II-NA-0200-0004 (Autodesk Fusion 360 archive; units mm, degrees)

design "II-NA-0200-0004" references "POWER", "LED", "3M Screw", "2 ports ethernet vertical", "Digitus_DN-651107_LAN-Switch 19.5mm"
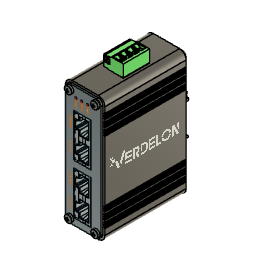
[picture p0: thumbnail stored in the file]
sketch "Sketch1" plane through (0, 0, 0) normal (0, 1, 0) x axis (1, 0, 0)
  line L1 (25, 0) -> (5, 0)
  line L2 (30, -90) -> (30, -5)
  line L3 (5, -95) -> (25, -95)
  line L4 (0, -5) -> (0, -90)
  arc A1 centre (5, -90) radius 5 clockwise from (5, -95) to (0, -90)
  arc A2 centre (25, -90) radius 5 clockwise from (30, -90) to (25, -95)
  arc A3 centre (5, -5) radius 5 clockwise from (0, -5) to (5, 0)
  arc A4 centre (25, -5) radius 5 clockwise from (25, 0) to (30, -5)
  point P1 (0, 0)
  point P2 (0, 0)
  point P4 (0, -95)
  point P3 (30, 0)
  horizontal L1
  vertical L2
  horizontal L3
  vertical L4
  coincident P1 P2
  coincident P4 L3
  coincident P4 L4
  tangent L3 A1
  tangent L4 A1
  tangent L2 A2
  tangent L3 A2
  equal A1 A2
  coincident P2 L1
  coincident P2 L4
  tangent L1 A3
  tangent L4 A3
  equal A1 A3
  coincident P3 L1
  coincident P3 L2
  tangent L1 A4
  tangent L2 A4
  equal A1 A4
  dimension "d1" distance P2 P4 = 95
  dimension "d2" distance P2 P3 = 30
  dimension "d3" radius A1 = 5
extrude "Extrude1" new body sketch "Sketch1" along normal blind 65
sketch "Sketch2" plane through (0, 0, 0) normal (0, -1, 0) x axis (1, 0, 0)
  line L1 (5, 95) -> (25, 95)
  line L2 (0, 5) -> (0, 90)
  line L3 (25, 0) -> (5, 0)
  line L4 (30, 90) -> (30, 5)
  line L5 (1.5, 5) -> (1.5, 90)
  line L6 (25, 1.5) -> (5, 1.5)
  line L7 (28.5, 90) -> (28.5, 5)
  line L8 (5, 93.5) -> (25, 93.5)
  line L9 (0, 5) -> (0, 90)
  line L10 (25, 0) -> (5, 0)
  line L11 (30, 90) -> (30, 5)
  line L12 (5, 95) -> (25, 95)
  arc A1 centre (25, 90) radius 5 clockwise from (25, 95) to (30, 90)
  arc A2 centre (5, 90) radius 5 clockwise from (0, 90) to (5, 95)
  arc A3 centre (5, 5) radius 5 clockwise from (5, 0) to (0, 5)
  arc A4 centre (25, 5) radius 5 clockwise from (30, 5) to (25, 0)
  arc A5 centre (5, 5) radius 3.5 clockwise from (5, 1.5) to (1.5, 5)
  arc A6 centre (25, 5) radius 3.5 clockwise from (28.5, 5) to (25, 1.5)
  arc A7 centre (25, 90) radius 3.5 clockwise from (25, 93.5) to (28.5, 90)
  arc A8 centre (5, 90) radius 3.5 clockwise from (1.5, 90) to (5, 93.5)
  arc A9 centre (5, 5) radius 5 clockwise from (5, 0) to (0, 5)
  arc A10 centre (25, 5) radius 5 clockwise from (30, 5) to (25, 0)
  arc A11 centre (25, 90) radius 5 clockwise from (25, 95) to (30, 90)
  arc A12 centre (5, 90) radius 5 clockwise from (0, 90) to (5, 95)
  dimension "d6" = -1.5
  dimension "d7" distance L2 = 0
extrude "Extrude2" cut sketch "Sketch2" against normal blind 1.5
sketch "Sketch3" plane through (0, 65, 0) normal (0, 1, 0) x axis (-1, 0, 0)
  line L1 (-30, 5) -> (-30, 90)
  line L2 (-5, 0) -> (-25, 0)
  line L3 (0, 90) -> (0, 5)
  line L4 (-25, 95) -> (-5, 95)
  line L5 (-28.5, 5) -> (-28.5, 90)
  line L6 (-5, 1.5) -> (-25, 1.5)
  line L7 (-1.5, 90) -> (-1.5, 5)
  line L8 (-25, 93.5) -> (-5, 93.5)
  line L9 (-30, 5) -> (-30, 90)
  line L10 (-5, 0) -> (-25, 0)
  line L11 (0, 90) -> (0, 5)
  line L12 (-25, 95) -> (-5, 95)
  arc A1 centre (-25, 90) radius 5 clockwise from (-30, 90) to (-25, 95)
  arc A2 centre (-25, 5) radius 5 clockwise from (-25, 0) to (-30, 5)
  arc A3 centre (-5, 5) radius 5 clockwise from (0, 5) to (-5, 0)
  arc A4 centre (-5, 90) radius 5 clockwise from (-5, 95) to (0, 90)
  arc A5 centre (-25, 5) radius 3.5 clockwise from (-25, 1.5) to (-28.5, 5)
  arc A6 centre (-5, 5) radius 3.5 clockwise from (-1.5, 5) to (-5, 1.5)
  arc A7 centre (-5, 90) radius 3.5 clockwise from (-5, 93.5) to (-1.5, 90)
  arc A8 centre (-25, 90) radius 3.5 clockwise from (-28.5, 90) to (-25, 93.5)
  arc A9 centre (-25, 5) radius 5 clockwise from (-25, 0) to (-30, 5)
  arc A10 centre (-5, 5) radius 5 clockwise from (0, 5) to (-5, 0)
  arc A11 centre (-5, 90) radius 5 clockwise from (-5, 95) to (0, 90)
  arc A12 centre (-25, 90) radius 5 clockwise from (-30, 90) to (-25, 95)
  dimension "d10" = -1.5
  dimension "d11" distance L1 = 0
extrude "Extrude3" cut sketch "Sketch3" against normal blind 1.5
sketch "Sketch4" plane through (0, 1.5, 0) normal (0, -1, 0) x axis (1, 0, 0)
  line L1 (25, 93.5) -> (5, 93.5)
  line L2 (28.5, 5) -> (28.5, 90)
  line L3 (5, 1.5) -> (25, 1.5)
  line L4 (1.5, 90) -> (1.5, 5)
  line L5 (0, 5) -> (0, 90)
  line L6 (25, 0) -> (5, 0)
  line L7 (30, 90) -> (30, 5)
  line L8 (5, 95) -> (25, 95)
  line L9 (-15.934, 47.5) -> (1.5, 47.5)
  line L10 (15, 105) -> (15, 93.5)
  line L11 (0.5, 85.5) -> (0, 85.5)
  line L12 (0.5, 84.5) -> (0.5, 85.5)
  line L13 (0, 84.5) -> (0.5, 84.5)
  line L14 (0, 85.5) -> (0, 84.5)
  line L15 (0, 84) -> (0, 83)
  line L16 (0, 83) -> (0.5, 83)
  line L17 (0.5, 84) -> (0, 84)
  line L18 (0.5, 83) -> (0.5, 84)
  line L19 (0, 82.5) -> (0, 81.5)
  line L20 (0, 81.5) -> (0.5, 81.5)
  line L21 (0.5, 82.5) -> (0, 82.5)
  line L22 (0.5, 81.5) -> (0.5, 82.5)
  line L23 (0, 79) -> (0.5, 79)
  line L24 (0, 77) -> (0, 76)
  line L25 (0, 78.5) -> (0, 77.5)
  line L26 (0.5, 78.5) -> (0, 78.5)
  line L27 (0.5, 80) -> (0, 80)
  line L28 (0, 76) -> (0.5, 76)
  line L29 (0.5, 76) -> (0.5, 77)
  line L30 (0, 80) -> (0, 79)
  line L31 (0.5, 77) -> (0, 77)
  line L32 (0, 77.5) -> (0.5, 77.5)
  line L33 (0.5, 77.5) -> (0.5, 78.5)
  line L34 (0.5, 79) -> (0.5, 80)
  line L35 (0, 73.5) -> (0.5, 73.5)
  line L36 (0, 71.5) -> (0, 70.5)
  line L37 (0, 73) -> (0, 72)
  line L38 (0.5, 73) -> (0, 73)
  line L39 (0.5, 74.5) -> (0, 74.5)
  line L40 (0, 70.5) -> (0.5, 70.5)
  line L41 (0.5, 70.5) -> (0.5, 71.5)
  line L42 (0, 74.5) -> (0, 73.5)
  line L43 (0.5, 71.5) -> (0, 71.5)
  line L44 (0, 72) -> (0.5, 72)
  line L45 (0.5, 72) -> (0.5, 73)
  line L46 (0.5, 73.5) -> (0.5, 74.5)
  line L47 (0, 23.5) -> (0, 24.5)
  line L48 (0.5, 17.5) -> (0.5, 16.5)
  line L49 (0.5, 19) -> (0.5, 18)
  line L50 (0, 20.5) -> (0, 21.5)
  line L51 (0, 16) -> (0.5, 16)
  line L52 (0.5, 11) -> (0, 11)
  line L53 (0.5, 12) -> (0.5, 11)
  line L54 (0, 12) -> (0.5, 12)
  line L55 (0.5, 15) -> (0, 15)
  line L56 (0, 15) -> (0, 16)
  line L57 (0, 17.5) -> (0.5, 17.5)
  line L58 (0, 19) -> (0.5, 19)
  line L59 (0.5, 16) -> (0.5, 15)
  line L60 (0, 11) -> (0, 12)
  line L61 (0, 22) -> (0, 23)
  line L62 (0.5, 18) -> (0, 18)
  line L63 (0, 13.5) -> (0.5, 13.5)
  line L64 (0.5, 23) -> (0.5, 22)
  line L65 (0.5, 10.5) -> (0.5, 9.5)
  line L66 (0, 10.5) -> (0.5, 10.5)
  line L67 (0.5, 23.5) -> (0, 23.5)
  line L68 (0.5, 12.5) -> (0, 12.5)
  line L69 (0.5, 21.5) -> (0.5, 20.5)
  line L70 (0.5, 16.5) -> (0, 16.5)
  line L71 (0, 12.5) -> (0, 13.5)
  line L72 (0, 16.5) -> (0, 17.5)
  line L73 (0, 24.5) -> (0.5, 24.5)
  line L74 (0.5, 24.5) -> (0.5, 23.5)
  line L75 (0, 21.5) -> (0.5, 21.5)
  line L76 (0.5, 9.5) -> (0, 9.5)
  line L77 (0.5, 13.5) -> (0.5, 12.5)
  line L78 (0, 9.5) -> (0, 10.5)
  line L79 (0, 18) -> (0, 19)
  line L80 (0.5, 22) -> (0, 22)
  line L81 (0.5, 20.5) -> (0, 20.5)
  line L82 (0, 23) -> (0.5, 23)
  line L83 (30, 76) -> (29.5, 76)
  line L84 (30, 70.5) -> (29.5, 70.5)
  line L85 (29.5, 73.5) -> (29.5, 74.5)
  line L86 (30, 84.5) -> (29.5, 84.5)
  line L87 (30, 73) -> (30, 72)
  line L88 (30, 83) -> (29.5, 83)
  line L89 (30, 72) -> (29.5, 72)
  line L90 (30, 73.5) -> (29.5, 73.5)
  line L91 (29.5, 83) -> (29.5, 84)
  line L92 (29.5, 77) -> (30, 77)
  line L93 (30, 71.5) -> (30, 70.5)
  line L94 (30, 78.5) -> (30, 77.5)
  line L95 (29.5, 73) -> (30, 73)
  line L96 (29.5, 82.5) -> (30, 82.5)
  line L97 (30, 81.5) -> (29.5, 81.5)
  line L98 (29.5, 84) -> (30, 84)
  line L99 (29.5, 77.5) -> (29.5, 78.5)
  line L100 (30, 79) -> (29.5, 79)
  line L101 (29.5, 84.5) -> (29.5, 85.5)
  line L102 (30, 77) -> (30, 76)
  line L103 (30, 74.5) -> (30, 73.5)
  line L104 (29.5, 79) -> (29.5, 80)
  line L105 (29.5, 81.5) -> (29.5, 82.5)
  line L106 (30, 80) -> (30, 79)
  line L107 (29.5, 85.5) -> (30, 85.5)
  line L108 (30, 85.5) -> (30, 84.5)
  line L109 (29.5, 76) -> (29.5, 77)
  line L110 (30, 84) -> (30, 83)
  line L111 (29.5, 71.5) -> (30, 71.5)
  line L112 (29.5, 78.5) -> (30, 78.5)
  line L113 (29.5, 70.5) -> (29.5, 71.5)
  line L114 (30, 82.5) -> (30, 81.5)
  line L115 (29.5, 80) -> (30, 80)
  line L116 (29.5, 74.5) -> (30, 74.5)
  line L117 (30, 77.5) -> (29.5, 77.5)
  line L118 (29.5, 72) -> (29.5, 73)
  line L119 (30, 17.5) -> (29.5, 17.5)
  line L120 (29.5, 23.5) -> (30, 23.5)
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  point P22 (1.5, 47.5)
  point P24 (15, 93.5)
  point P26 (0, 85.5)
  point P81 (0, 9.5)
  point P27 (0.5, 85.5)
  point P73 (0.5, 9.5)
  point P28 (0.5, 84.5)
  point P67 (0.5, 10.5)
  point P29 (0, 84.5)
  point P89 (0, 10.5)
  point P30 (0, 83)
  point P91 (0, 12)
  point P31 (0, 84)
  point P86 (0, 11)
  point P32 (0.5, 83)
  point P65 (0.5, 12)
  point P33 (0.5, 84)
  point P77 (0.5, 11)
  point P34 (0, 81.5)
  point P70 (0, 13.5)
  point P35 (0, 82.5)
  point P68 (0, 12.5)
  point P36 (0.5, 81.5)
  point P80 (0.5, 13.5)
  point P37 (0.5, 82.5)
  point P82 (0.5, 12.5)
  point P38 (0, 79)
  point P83 (0, 16)
  point P39 (0.5, 79)
  point P76 (0.5, 16)
  point P40 (0.5, 80)
  point P74 (0.5, 15)
  point P41 (0, 76)
  point P71 (0, 19)
  point P42 (0, 77)
  point P62 (0, 18)
  point P43 (0.5, 77)
  point P63 (0.5, 18)
  point P44 (0, 77.5)
  point P93 (0, 17.5)
  point P45 (0, 78.5)
  point P92 (0, 16.5)
  point P46 (0.5, 78.5)
  point P90 (0.5, 16.5)
  point P47 (0, 80)
  point P96 (0, 15)
  point P48 (0.5, 76)
  point P95 (0.5, 19)
  point P49 (0.5, 77.5)
  point P97 (0.5, 17.5)
  point P50 (0, 73.5)
  point P87 (0, 21.5)
  point P51 (0.5, 73.5)
  point P88 (0.5, 21.5)
  point P52 (0.5, 74.5)
  point P94 (0.5, 20.5)
  point P53 (0, 70.5)
  point P66 (0, 24.5)
  point P54 (0, 71.5)
  point P64 (0, 23.5)
  point P55 (0.5, 71.5)
  point P78 (0.5, 23.5)
  point P56 (0, 72)
  point P72 (0, 23)
  point P57 (0, 73)
  point P75 (0, 22)
  point P58 (0.5, 73)
  point P69 (0.5, 22)
  point P59 (0, 74.5)
  point P79 (0, 20.5)
  point P60 (0.5, 70.5)
  point P84 (0.5, 24.5)
  point P61 (0.5, 72)
  point P85 (0.5, 23)
  point P106 (30, 85.5)
  point P121 (29.5, 85.5)
  point P122 (29.5, 84.5)
  point P118 (30, 84.5)
  point P120 (30, 83)
  point P119 (30, 84)
  point P123 (29.5, 83)
  point P126 (29.5, 84)
  point P125 (30, 81.5)
  point P124 (30, 82.5)
  point P100 (29.5, 81.5)
  point P98 (29.5, 82.5)
  point P102 (30, 79)
  point P99 (29.5, 79)
  point P101 (29.5, 80)
  point P131 (30, 76)
  point P129 (30, 77)
  point P127 (29.5, 77)
  point P130 (30, 77.5)
  point P133 (30, 78.5)
  point P128 (29.5, 78.5)
  point P132 (30, 80)
  point P113 (29.5, 76)
  point P116 (29.5, 77.5)
  point P112 (30, 73.5)
  point P117 (29.5, 73.5)
  point P115 (29.5, 74.5)
  point P114 (30, 70.5)
  point P111 (30, 71.5)
  point P105 (29.5, 71.5)
  point P108 (30, 72)
  point P104 (30, 73)
  point P103 (29.5, 73)
  point P109 (30, 74.5)
  point P110 (29.5, 70.5)
  point P107 (29.5, 72)
  point P169 (30, 18)
  point P134 (29.5, 18)
  point P138 (30, 23.5)
  point P166 (29.5, 12)
  point P139 (30, 24.5)
  point P160 (29.5, 10.5)
  point P140 (30, 12.5)
  point P135 (29.5, 22)
  point P147 (30, 13.5)
  point P136 (30, 19)
  point P155 (30, 23)
  point P148 (29.5, 9.5)
  point P162 (29.5, 15)
  point P168 (30, 22)
  point P157 (29.5, 16)
  point P141 (29.5, 11)
  point P165 (29.5, 23.5)
  point P167 (30, 20.5)
  point P151 (29.5, 13.5)
  point P143 (30, 9.5)
  point P152 (29.5, 12.5)
  point P150 (30, 16)
  point P145 (29.5, 24.5)
  point P142 (29.5, 23)
  point P164 (30, 11)
  point P149 (30, 21.5)
  point P146 (29.5, 21.5)
  point P154 (30, 10.5)
  point P144 (29.5, 16.5)
  point P153 (30, 12)
  point P158 (30, 16.5)
  point P156 (30, 17.5)
  point P163 (29.5, 20.5)
  point P161 (29.5, 19)
  point P159 (30, 15)
  point P137 (29.5, 17.5)
  midpoint L4 P22
  perpendicular L4 L9
  midpoint L1 P24
  perpendicular L8 L10
  horizontal L11
  vertical L12
  horizontal L13
  vertical L14
  coincident L5 P26
  symmetric L9 P26 P81
  symmetric L9 P27 P73
  symmetric L9 P28 P67
  symmetric L9 P29 P89
  symmetric L9 P30 P91
  symmetric L9 P31 P86
  symmetric L9 P32 P65
  symmetric L9 P33 P77
  symmetric L9 P34 P70
  symmetric L9 P35 P68
  symmetric L9 P36 P80
  symmetric L9 P37 P82
  symmetric L9 P38 P83
  symmetric L9 P39 P76
  symmetric L9 P40 P74
  symmetric L9 P41 P71
  symmetric L9 P42 P62
  symmetric L9 P43 P63
  symmetric L9 P44 P93
  symmetric L9 P45 P92
  symmetric L9 P46 P90
  symmetric L9 P47 P96
  symmetric L9 P48 P95
  symmetric L9 P49 P97
  symmetric L9 P50 P87
  symmetric L9 P51 P88
  symmetric L9 P52 P94
  symmetric L9 P53 P66
  symmetric L9 P54 P64
  symmetric L9 P55 P78
  symmetric L9 P56 P72
  symmetric L9 P57 P75
  symmetric L9 P58 P69
  symmetric L9 P59 P79
  symmetric L9 P60 P84
  symmetric L9 P61 P85
  symmetric L10 P26 P106
  symmetric L10 P27 P121
  symmetric L10 P28 P122
  symmetric L10 P29 P118
  symmetric L10 P30 P120
  symmetric L10 P31 P119
  symmetric L10 P32 P123
  symmetric L10 P33 P126
  symmetric L10 P34 P125
  symmetric L10 P35 P124
  symmetric L10 P36 P100
  symmetric L10 P37 P98
  symmetric L10 P38 P102
  symmetric L10 P39 P99
  symmetric L10 P40 P101
  symmetric L10 P41 P131
  symmetric L10 P42 P129
  symmetric L10 P43 P127
  symmetric L10 P44 P130
  symmetric L10 P45 P133
  symmetric L10 P46 P128
  symmetric L10 P47 P132
  symmetric L10 P48 P113
  symmetric L10 P49 P116
  symmetric L10 P50 P112
  symmetric L10 P51 P117
  symmetric L10 P52 P115
  symmetric L10 P53 P114
  symmetric L10 P54 P111
  symmetric L10 P55 P105
  symmetric L10 P56 P108
  symmetric L10 P57 P104
  symmetric L10 P58 P103
  symmetric L10 P59 P109
  symmetric L10 P60 P110
  symmetric L10 P61 P107
  symmetric L10 P62 P169
  symmetric L10 P63 P134
  symmetric L10 P64 P138
  symmetric L10 P65 P166
  symmetric L10 P66 P139
  symmetric L10 P67 P160
  symmetric L10 P68 P140
  symmetric L10 P69 P135
  symmetric L10 P70 P147
  symmetric L10 P71 P136
  symmetric L10 P72 P155
  symmetric L10 P73 P148
  symmetric L10 P74 P162
  symmetric L10 P75 P168
  symmetric L10 P76 P157
  symmetric L10 P77 P141
  symmetric L10 P78 P165
  symmetric L10 P79 P167
  symmetric L10 P80 P151
  symmetric L10 P81 P143
  symmetric L10 P82 P152
  symmetric L10 P83 P150
  symmetric L10 P84 P145
  symmetric L10 P85 P142
  symmetric L10 P86 P164
  symmetric L10 P87 P149
  symmetric L10 P88 P146
  symmetric L10 P89 P154
  symmetric L10 P90 P144
  symmetric L10 P91 P153
  symmetric L10 P92 P158
  symmetric L10 P93 P156
  symmetric L10 P94 P163
  symmetric L10 P95 P161
  symmetric L10 P96 P159
  symmetric L10 P97 P137
  dimension "d14" distance P26 P29 = 1
  dimension "d15" distance P26 P27 = 0.5
  dimension "d24" distance L9 L40 = 23
  dimension "d18" R-Pattern1-uDistance = 0
  dimension "d19" R-Pattern1-vDistance = -3
  dimension "d22" R-Pattern2-uDistance = 0
  dimension "d23" R-Pattern2-vDistance = -11
extrude "Extrude4" cut sketch "Sketch4" against normal blind 64
sketch "Sketch10" plane through (0, 0, 0) normal (0, -1, 0) x axis (1, 0, 0)
  line L1 (5, 93.5) -> (25, 93.5)
  line L2 (1.5, 5) -> (1.5, 90)
  line L3 (25, 1.5) -> (5, 1.5)
  line L4 (28.5, 90) -> (28.5, 5)
  line L5 (15, 47.5) -> (15, 93.5)
  line L6 (15, 47.5) -> (1.5, 47.5)
  line L7 (21.58, 80.5) -> (8.42, 80.5)
  line L8 (21.58, 64.09) -> (21.58, 80.5)
  line L9 (8.42, 64.09) -> (21.58, 64.09)
  line L10 (8.42, 80.5) -> (8.42, 64.09)
  line L11 (8.42, 55.5) -> (8.42, 39.09)
  line L12 (8.42, 39.09) -> (21.58, 39.09)
  line L13 (21.58, 39.09) -> (21.58, 55.5)
  line L14 (21.58, 55.5) -> (8.42, 55.5)
  line L15 (18.075, 22) -> (11.925, 22)
  line L16 (18.075, 14.12) -> (18.075, 22)
  line L17 (11.925, 14.12) -> (18.075, 14.12)
  line L18 (11.925, 22) -> (11.925, 14.12)
  line L19 (10, 18.06) -> (11.925, 18.06)
  line L20 (15, 15.6742) -> (15, 14.12)
  arc A1 centre (5, 90) radius 3.5 clockwise from (1.5, 90) to (5, 93.5)
  arc A2 centre (5, 5) radius 3.5 clockwise from (5, 1.5) to (1.5, 5)
  arc A3 centre (25, 5) radius 3.5 clockwise from (28.5, 5) to (25, 1.5)
  arc A4 centre (25, 90) radius 3.5 clockwise from (25, 93.5) to (28.5, 90)
  circle C1 centre (10.42, 34.09) radius 0.75
  circle C2 centre (14.42, 34.09) radius 0.75
  circle C3 centre (5, 90) radius 1.5
  circle C4 centre (25, 90) radius 1.5
  circle C5 centre (5, 5) radius 1.5
  circle C6 centre (25, 5) radius 1.5
  circle C7 centre (15.1004, 11.1) radius 1.3
  circle C8 centre (15.1004, 25.02) radius 1.3
  point P14 (15, 93.5)
  point P15 (1.5, 47.5)
  point P36 (11.925, 18.06)
  point P39 (15, 14.12)
  point P17 (8.42, 80.5)
  point P20 (8.42, 64.09)
  point P18 (21.58, 80.5)
  point P25 (10.42, 34.09)
  point P31 (11.925, 22)
  point P34 (11.925, 14.12)
  point P32 (18.075, 22)
  point P35 (15.1004, 11.1)
  midpoint L1 P14
  perpendicular L1 L5
  midpoint L2 P15
  perpendicular L2 L6
  horizontal L7
  vertical L8
  horizontal L9
  vertical L10
  symmetric L5 L8 L10
  concentric A1 C3
  horizontal L15
  vertical L16
  horizontal L17
  vertical L18
  symmetric L5 L16 L18
  midpoint L18 P36
  perpendicular L18 L19
  symmetric C7 L19 C8
  midpoint L17 P39
  perpendicular L17 L20
  dimension "d99" distance P17 P20 = 16.41
  dimension "d100" distance P17 P18 = 13.16
  dimension "d105" diameter C1 = 1.5
  dimension "d110" distance L6 L14 = 8
  dimension "d111" distance L12 P25 = 5
  dimension "d112" distance L11 P25 = 2
  dimension "d113" diameter C3 = 3
  dimension "d122" distance P31 P34 = 7.88
  dimension "d123" distance P31 P32 = 6.15
  dimension "d124" diameter C7 = 2.6
  dimension "d125" distance L17 P35 = 3.02
  dimension "d126" distance L6 L15 = 25.5
  dimension "d127" distance P34 P35 = 3.1754
  dimension "d103" R-Pattern1-uDistance = 0
  dimension "d104" R-Pattern1-vDistance = -25
  dimension "d108" R-Pattern2-uDistance = 4
  dimension "d109" R-Pattern2-vDistance = 0
  dimension "d116" R-Pattern3-uDistance = 20
  dimension "d117" R-Pattern3-vDistance = 0
  dimension "d120" R-Pattern4-uDistance = 0
  dimension "d121" R-Pattern4-vDistance = -85
sketch "Sketch12" plane through (0, 0, 0) normal (0, -1, 0) x axis (1, 0, 0)
  line L1 (5, 93.5) -> (25, 93.5)
  line L2 (1.5, 5) -> (1.5, 90)
  line L3 (25, 1.5) -> (5, 1.5)
  line L4 (28.5, 90) -> (28.5, 5)
  line L5 (15, 47.5) -> (15, 93.5)
  line L6 (15, 47.5) -> (1.5, 47.5)
  line L7 (21, 77.32) -> (7.84, 77.32)
  line L8 (21, 44.5) -> (21, 77.32)
  line L9 (7.84, 44.5) -> (21, 44.5)
  line L10 (7.84, 77.32) -> (7.84, 44.5)
  line L11 (21, 39.32) -> (7.84, 39.32)
  line L12 (7.84, 39.32) -> (7.84, 6.5)
  line L13 (21, 6.5) -> (21, 39.32)
  line L14 (7.84, 6.5) -> (21, 6.5)
  arc A1 centre (5, 90) radius 3.5 clockwise from (1.5, 90) to (5, 93.5)
  arc A2 centre (5, 5) radius 3.5 clockwise from (5, 1.5) to (1.5, 5)
  arc A3 centre (25, 5) radius 3.5 clockwise from (28.5, 5) to (25, 1.5)
  arc A4 centre (25, 90) radius 3.5 clockwise from (25, 93.5) to (28.5, 90)
  circle C1 centre (9.34, 86.32) radius 0.75
  circle C2 centre (13.84, 86.32) radius 0.75
  circle C3 centre (18.34, 86.32) radius 0.75
  circle C4 centre (5, 90) radius 1.5
  circle C5 centre (25, 90) radius 1.5
  circle C6 centre (5, 5) radius 1.5
  circle C7 centre (25, 5) radius 1.5
  point P14 (15, 93.5)
  point P15 (1.5, 47.5)
  point P17 (7.84, 77.32)
  point P20 (7.84, 44.5)
  point P18 (21, 77.32)
  point P25 (9.34, 86.32)
  midpoint L1 P14
  perpendicular L1 L5
  midpoint L2 P15
  perpendicular L2 L6
  horizontal L7
  vertical L8
  horizontal L9
  vertical L10
  concentric A1 C4
  dimension "d158" distance P17 P20 = 32.82
  dimension "d159" distance P17 P18 = 13.16
  dimension "d164" distance L5 L8 = 6
  dimension "d165" distance L6 L9 = 3
  dimension "d166" diameter C1 = 1.5
  dimension "d167" distance L7 P25 = 9
  dimension "d168" distance L10 P25 = 1.5
  dimension "d176" diameter C4 = 3
  dimension "d162" R-Pattern1-uDistance = 0
  dimension "d163" R-Pattern1-vDistance = -38
  dimension "d171" R-Pattern2-uDistance = 9
  dimension "d172" R-Pattern2-vDistance = 0
  dimension "d179" R-Pattern3-uDistance = 20
  dimension "d180" R-Pattern3-vDistance = 0
  dimension "d183" R-Pattern4-uDistance = 0
  dimension "d184" R-Pattern4-vDistance = -85
extrude "Extrude8" cut sketch "Sketch12" profile of L5 L6 L7 L8 L9 L10 L11 L12 L13 L14 C1 C2 C3 C4 C5 C6 C7 against normal blind 3
shell "Shell3" innerThickness 1
sketch "Sketch13" plane through (0, 0, 95) normal (0, 0, 1) x axis (-1, 0, 0)
  line L1 (-5, -63.5) -> (-25, -63.5)
  line L2 (-5, -1.5) -> (-5, -63.5)
  line L3 (-25, -1.5) -> (-5, -1.5)
  line L4 (-25, -63.5) -> (-25, -1.5)
  line L5 (-15, -32.5) -> (-15, -63.5)
  line L6 (-15, -32.5) -> (-5, -32.5)
  line L7 (-23.17, -42.5) -> (-15.5, -42.5)
  line L8 (-23.17, -22.5) -> (-23.17, -42.5)
  line L9 (-15.5, -22.5) -> (-23.17, -22.5)
  line L10 (-15.5, -42.5) -> (-15.5, -22.5)
  point P6 (-15, -63.5)
  point P7 (-5, -32.5)
  point P10 (-23.17, -42.5)
  point P11 (-23.17, -22.5)
  point P9 (-15.5, -42.5)
  midpoint L1 P6
  perpendicular L1 L5
  midpoint L2 P7
  perpendicular L2 L6
  horizontal L7
  vertical L8
  horizontal L9
  vertical L10
  symmetric L6 L7 L9
  dimension "d193" distance P10 P11 = 20
  dimension "d194" distance P9 P10 = 7.67
  dimension "d195" distance L5 L10 = 0.5
extrude "Extrude9" cut sketch "Sketch13" profile of L7 L8 L9 L10 against normal blind 5
component_insert "Component Insert3"
component_insert "Component Insert10"
position "Position2"
joint "Assemble4" alignAngle 0 alignOffsetX 0 alignOffsetY 0 alignOffsetZ 1.5
rectangular_pattern "00000000-0000-0000-0000-000000000000" uSpaceDistance 9 vSpaceDistance 0
component_insert "Component Insert17"
position "Position4"
rectangular_pattern "00000000-0000-0000-0000-000000000000" uSpaceDistance 20 vSpaceDistance 0
rectangular_pattern "00000000-0000-0000-0000-000000000000" uSpaceDistance -85 vSpaceDistance 0
component_insert "Component Insert18"
position "Position5"
rectangular_pattern "00000000-0000-0000-0000-000000000000" uSpaceDistance 38 vSpaceDistance 0
component_insert "Component Insert20"
decal "Decal1"
decal "Decal2"
position "Position6"
sketch "Sketch14" plane through (0, 0, 0) normal (0, -1, 0) x axis (1, 0, 0)
  dimension "d202" = 1
  dimension "d203" = 1
  dimension "d204" = 1
  dimension "d205" = 1
  dimension "d206" = 1
  dimension "d207" = 1
  dimension "d208" = 1
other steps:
joint_origin "JointOrigin4"
step "Component Insert"

design "3M Screw"
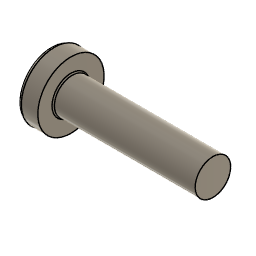
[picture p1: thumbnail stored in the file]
description: STEP AP214
part number: 3M Screw

design "POWER"
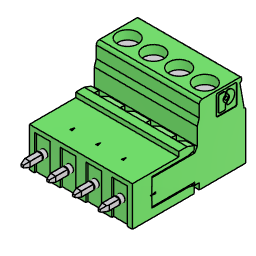
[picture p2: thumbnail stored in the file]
description: STEP AP214
part number: POWER

design "Digitus_DN-651107_LAN-Switch 19.5mm"
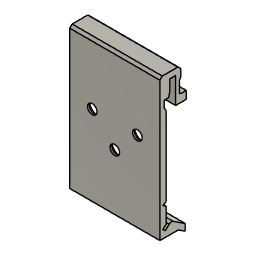
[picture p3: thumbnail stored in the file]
description: STEP AP214
part number: Digitus_DN-651107_LAN-Switch 19.5mm

design "2 ports ethernet vertical"
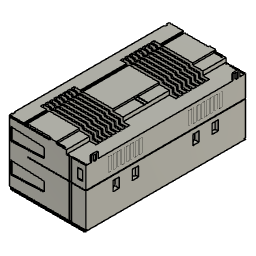
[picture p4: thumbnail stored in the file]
description: STEP AP214
part number: 2 ports ethernet vertical

design "LED"
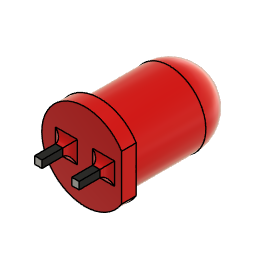
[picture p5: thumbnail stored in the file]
description: STEP AP214
part number: LED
